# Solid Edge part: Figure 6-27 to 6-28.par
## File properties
Author: CADCIM
Template: Normal.par
Last saved by: Ashutosh-CADCIM
Revision: 7
Application: Solid Edge
Accuracy: 0.99
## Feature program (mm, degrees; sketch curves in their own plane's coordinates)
sketch for "unnamed Protrusion 1" plane through (0, 0, 0) normal (0, 0, 1) x-axis (1, 0, 0)
  line (-52.1766, -31.6987) -> (52.1766, -31.6987)
  line (52.1766, -31.6987) -> (52.1766, 31.6987)
  line (52.1766, 31.6987) -> (-52.1766, 31.6987)
  line (-52.1766, 31.6987) -> (-52.1766, -31.6987)
extrude "unnamed Protrusion 1" add finite 57.15 along +normal
sketch for "ExtrudedCutout_1" plane through (0, 0, 57.15) normal (0, 0, 1) x-axis (0, 1, 0)
  line (-31.6987, 0) -> (8.7819, 0)
  line (8.7819, 0) -> (8.7819, -52.1766)
extrude "ExtrudedCutout_1" cut finite 41.275 along -normal
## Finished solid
Body 1: solid body, 9 faces, 21 edges, 14 vertices.
  Faces by surface: plane 9
  Edges by curve: line 21
Bounding box of the edges (mm): 104.353 x 63.397 x 57.150, from (-52.1766, -31.6987, 0) to (52.1766, 31.6987, 57.15).
Planar faces by outward normal: +x 2, +y 1, +z 2, -x 1, -y 2, -z 1
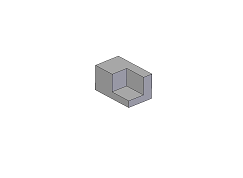
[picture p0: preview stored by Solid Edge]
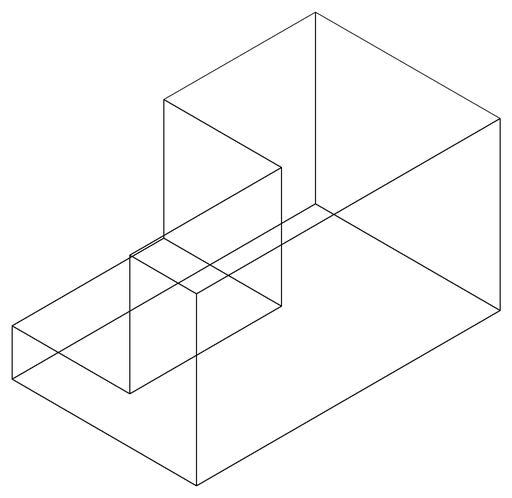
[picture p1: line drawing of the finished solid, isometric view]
